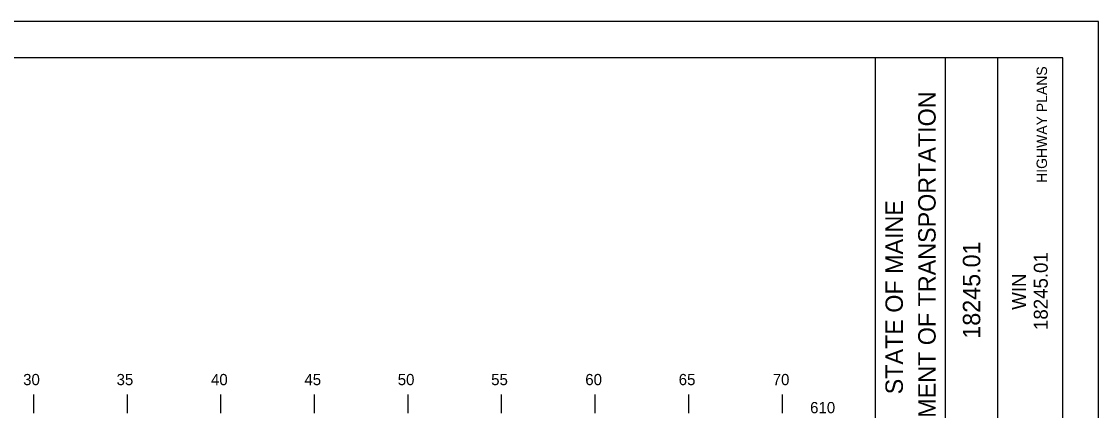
# Model space of a CAD drawing. Extents: x 1073421 to 1073591, y 779716 to 779826.
# Drawn here: x 1073533.3 to 1073590.9, y 779804.9 to 779825.6 of the extents above; entities that cross this region are included whole.
import ezdxf

# ---------------------------------------------------------------- set-up
doc = ezdxf.new("R2010")
doc.units = 0
for name, color, linetype in [('BORDER', 7, 'Continuous'), ('H_V ANNOTATION', 7, 'Continuous'), ('HIGHWAY_TITLE', 7, 'Continuous'), ('MAJOR', 7, 'Continuous'), ('PLOT BOUNDARY', 7, 'Continuous')]:
    doc.layers.add(name, color=color, linetype=linetype)

msp = doc.modelspace()

# ---------------------------------------------------------------- linework, layer by layer
at = {"layer": 'BORDER'}
for p, q in [((1073578.959, 779718.706), (1073578.959, 779823.706)), ((1073582.688, 779798.703), (1073582.688, 779823.703)), ((1073585.483, 779798.703), (1073585.483, 779823.703))]:
    msp.add_line(p, q, dxfattribs=at)
msp.add_lwpolyline([(1073428.959, 779718.706), (1073588.959, 779718.706), (1073588.959, 779823.706), (1073428.959, 779823.706)], close=True, dxfattribs=at)
at = {"layer": 'MAJOR'}
for p, q in [((1073533.959, 779805.708), (1073533.959, 779804.706)), ((1073538.959, 779805.708), (1073538.959, 779804.706)), ((1073543.959, 779805.708), (1073543.959, 779804.706)), ((1073548.959, 779805.708), (1073548.959, 779804.706)), ((1073553.959, 779805.708), (1073553.959, 779804.706)), ((1073558.959, 779805.708), (1073558.959, 779804.706)), ((1073563.959, 779805.708), (1073563.959, 779804.706)), ((1073568.959, 779805.708), (1073568.959, 779804.706)), ((1073573.959, 779805.708), (1073573.959, 779804.706))]:
    msp.add_line(p, q, dxfattribs=at)
at = {"layer": 'PLOT BOUNDARY'}
msp.add_lwpolyline([(1073420.866, 779715.646), (1073590.866, 779715.646), (1073590.866, 779825.646), (1073420.866, 779825.646)], close=True, dxfattribs=at)

# ---------------------------------------------------------------- texts
at = {"layer": 'BORDER'}
for s, height, p in [('DEPARTMENT OF TRANSPORTATION', 0.93176, (1073582.166, 779799.412)), ('DEPARTMENT OF TRANSPORTATION', 0.93176, (1073582.166, 779799.412)), ('STATE OF MAINE', 0.93176, (1073580.415, 779805.718)), ('STATE OF MAINE', 0.93176, (1073580.415, 779805.718)), ('18245.01', 0.9318, (1073584.551, 779808.691)), ('18245.01', 0.7453, (1073588.155, 779809.156)), ('WIN', 0.7453, (1073586.996, 779810.236))]:
    msp.add_text(s, height=height, rotation=90, dxfattribs=at).set_placement(p)
at = {"layer": 'H_V ANNOTATION'}
for s, p in [('30', (1073533.408, 779806.206)), ('35', (1073538.4, 779806.206)), ('40', (1073543.445, 779806.206)), ('45', (1073548.437, 779806.206)), ('50', (1073553.424, 779806.206)), ('55', (1073558.416, 779806.206)), ('60', (1073563.445, 779806.206)), ('65', (1073568.437, 779806.206)), ('70', (1073573.461, 779806.206)), ('610', (1073575.459, 779804.706))]:
    msp.add_text(s, height=0.6, dxfattribs=at).set_placement(p)
at = {"layer": 'HIGHWAY_TITLE'}
msp.add_text('HIGHWAY PLANS', height=0.55901, rotation=90, dxfattribs=at).set_placement((1073588.118, 779817.021))

doc.saveas('drawing.dxf')
